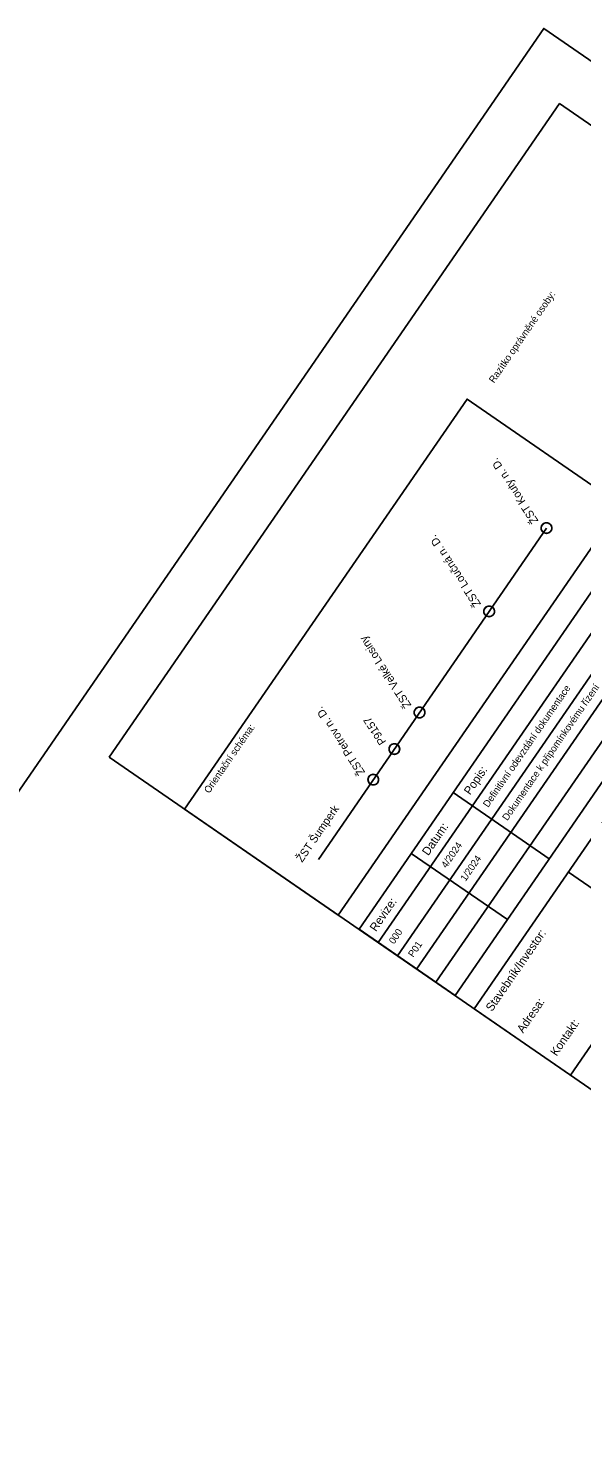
# Model space of a CAD drawing. Extents: x -558199 to -558019, y -1073463 to -1073248.
# Drawn here: x -558109.2 to -558078.1, y -1073327.4 to -1073247.5 of the extents above; entities that cross this region are included whole.
import ezdxf

# ---------------------------------------------------------------- set-up
doc = ezdxf.new("R2010")
doc.units = 0
for name, color, linetype in [('Default', 7, 'Continuous'), ('Rozpiska', 7, 'Continuous'), ('Rozpiska_pola_3', 7, 'Continuous'), ('Rozpiska_pole_1', 7, 'Continuous'), ('Rozpiska_pole_2', 7, 'Continuous'), ('Rozpiska_pole_4', 7, 'Continuous'), ('Rozpiska_pole_5', 7, 'Continuous'), ('Rozpiska_pole_6', 7, 'Continuous'), ('Rozpiska_pole_7', 7, 'Continuous'), ('Rámeček', 7, 'Continuous')]:
    doc.layers.add(name, color=color, linetype=linetype)

# ---------------------------------------------------------------- blocks, each defined once
blk = doc.blocks.new('_U3')
at = {"layer": 'Rozpiska_pola_3'}
blk.add_line((-26.675, -18.2505), (26.675, -18.2505), dxfattribs=at)
for s, p in [('Razítko oprávněné osoby:', (-25.675, 19.2495)), ('Podpis:', (-25.675, -20.7505)), ('Datum:', (8.325, -20.7505))]:
    blk.add_text(s, height=1.5, dxfattribs=at).set_placement(p)
blk = doc.blocks.new('_U7')
at = {"layer": 'Rozpiska_pole_2'}
blk.add_lwpolyline([(-53.3255, 20.0005), (53.3245, 20.0005), (53.3245, -19.9995), (-53.3255, -19.9995)], close=True, dxfattribs=at)
blk.add_text('Orientační schéma:', height=1.5, dxfattribs=at).set_placement((-47.6755, 17.5005))

msp = doc.modelspace()

# ---------------------------------------------------------------- linework, layer by layer
at = {"layer": 'Default'}
for centre in [(-558088.596, -1073288.057), (-558089.782, -1073289.778)]:
    msp.add_circle(centre, 0.3, dxfattribs=at)
at = {"layer": 'Rozpiska'}
msp.add_lwpolyline([(-558092.872, -1073294.263), (-558080.038, -1073275.632)], dxfattribs=at)
for centre in [(-558080.038, -1073275.632), (-558083.265, -1073280.316), (-558087.18, -1073286.001)]:
    msp.add_circle(centre, 0.3, dxfattribs=at)
for centre, start, end in [((-558080.041, -1073275.634), 55.43906, 235.43906), ((-558080.041, -1073275.634), 235.43906, 55.43906), ((-558083.268, -1073280.319), 55.43906, 235.43906), ((-558083.268, -1073280.319), 235.43906, 55.43906), ((-558087.184, -1073286.003), 55.43906, 235.43906), ((-558087.184, -1073286.003), 235.43906, 55.43906), ((-558088.6, -1073288.059), 55.43906, 235.43906), ((-558088.6, -1073288.059), 235.43906, 55.43906), ((-558089.786, -1073289.78), 55.43906, 235.43906), ((-558089.786, -1073289.78), 235.43906, 55.43906)]:
    msp.add_arc(centre, 0.3, start, end, dxfattribs=at)
at = {"layer": 'Rozpiska_pole_1'}
msp.add_lwpolyline([(-558104.635, -1073288.508), (-558079.308, -1073251.767), (-558023.115, -1073290.501), (-558048.441, -1073327.243)], close=True, dxfattribs=at)
at = {"layer": 'Rozpiska_pole_4'}
for p, q in [((-558089.506, -1073298.937), (-558064.179, -1073262.195)), ((-558088.425, -1073299.682), (-558063.099, -1073262.94)), ((-558087.344, -1073300.427), (-558062.018, -1073263.685)), ((-558086.264, -1073301.172), (-558060.937, -1073264.43)), ((-558079.887, -1073294.233), (-558085.29, -1073290.509)), ((-558082.241, -1073297.648), (-558087.644, -1073293.924))]:
    msp.add_line(p, q, dxfattribs=at)
msp.add_lwpolyline([(-558090.586, -1073298.192), (-558065.26, -1073261.45), (-558059.857, -1073265.175), (-558085.183, -1073301.917)], close=True, dxfattribs=at)
at = {"layer": 'Rozpiska_pole_5'}
msp.add_line((-558073.403, -1073298.703), (-558078.806, -1073294.978), dxfattribs=at)
msp.add_lwpolyline([(-558084.103, -1073302.661), (-558058.776, -1073265.92), (-558053.373, -1073269.644), (-558078.699, -1073306.386)], close=True, dxfattribs=at)
at = {"layer": 'Rámeček'}
msp.add_lwpolyline([(-558019.047, -1073289.661), (-558080.194, -1073247.54), (-558199.323, -1073420.48), (-558138.176, -1073462.601)], close=True, dxfattribs=at)

# ---------------------------------------------------------------- block references
at = {"layer": 'Rozpiska_pola_3', "xscale": 0.2625000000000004, "yscale": 0.26250000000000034, "rotation": 55.42136593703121}
msp.add_blockref('_U3', (-558075.004, -1073264.832), dxfattribs=at)
at = {"layer": 'Rozpiska_pole_2', "xscale": 0.2625000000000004, "yscale": 0.26250000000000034, "rotation": 55.42136593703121}
msp.add_blockref('_U7', (-558088.129, -1073282.885), dxfattribs=at)

# ---------------------------------------------------------------- texts
at = {"layer": 'Rozpiska_pole_4'}
for s, height, p in [('Definitivní odevzdání dokumentace', 0.39375, (-558083.321, -1073291.373)), ('Dokumentace k připomínkovému řízení', 0.39375, (-558082.24, -1073292.118)), ('Popis:', 0.4725, (-558084.336, -1073290.673)), ('Datum:', 0.4725, (-558086.69, -1073294.088)), ('4/2024', 0.3937, (-558085.675, -1073294.788)), ('1/2024', 0.3937, (-558084.594, -1073295.533)), ('Revize:', 0.4725, (-558089.633, -1073298.356)), ('000', 0.3937, (-558088.617, -1073299.057)), ('P01', 0.3937, (-558087.536, -1073299.802))]:
    msp.add_text(s, height=height, rotation=55.42137, dxfattribs=at).set_placement(p)
at = {"layer": 'Rozpiska_pole_5'}
for s, p in [('Stavebník/Investor:', (-558083.11, -1073302.853)), ('Adresa:', (-558081.356, -1073304.061))]:
    msp.add_text(s, height=0.4725, rotation=55.42137, dxfattribs=at).set_placement(p)
at = {"layer": 'Rozpiska_pole_6'}
msp.add_text('Kontakt:', height=0.4725, rotation=55.42137, dxfattribs=at).set_placement((-558079.474, -1073305.359))
at = {"layer": 'Rozpiska_pole_7'}
for s, rotation, p in [('ŽST Kouty n. D.', 123.31219, (-558080.482, -1073275.22)), ('ŽST Loučná n. D.', 123.31219, (-558083.709, -1073279.905)), ('ŽST Velké Losiny', 123.31219, (-558087.625, -1073285.589)), ('ŽST Petrov n. D.', 123.31219, (-558090.227, -1073289.366)), ('P9157', 123.31219, (-558089.041, -1073287.645)), ('ŽST Šumperk', 55.43906, (-558093.789, -1073294.467))]:
    msp.add_text(s, height=0.45, rotation=rotation, dxfattribs=at).set_placement(p)

doc.saveas('drawing.dxf')
